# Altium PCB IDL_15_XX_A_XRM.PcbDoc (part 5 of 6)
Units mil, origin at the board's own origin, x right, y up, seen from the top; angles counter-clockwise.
Board outline 6653.34 x 6653.34 mil, 6 copper layers (Top Layer - SIG1, Layer 2 - GND1, Layer 3 - PWR, Layer 4 - PWR, Layer 5 - GND2, Bottom Layer - SIG4), stack 59.843 mil thick; 613 components, 324 nets, 1673 pads, 2316 vias.
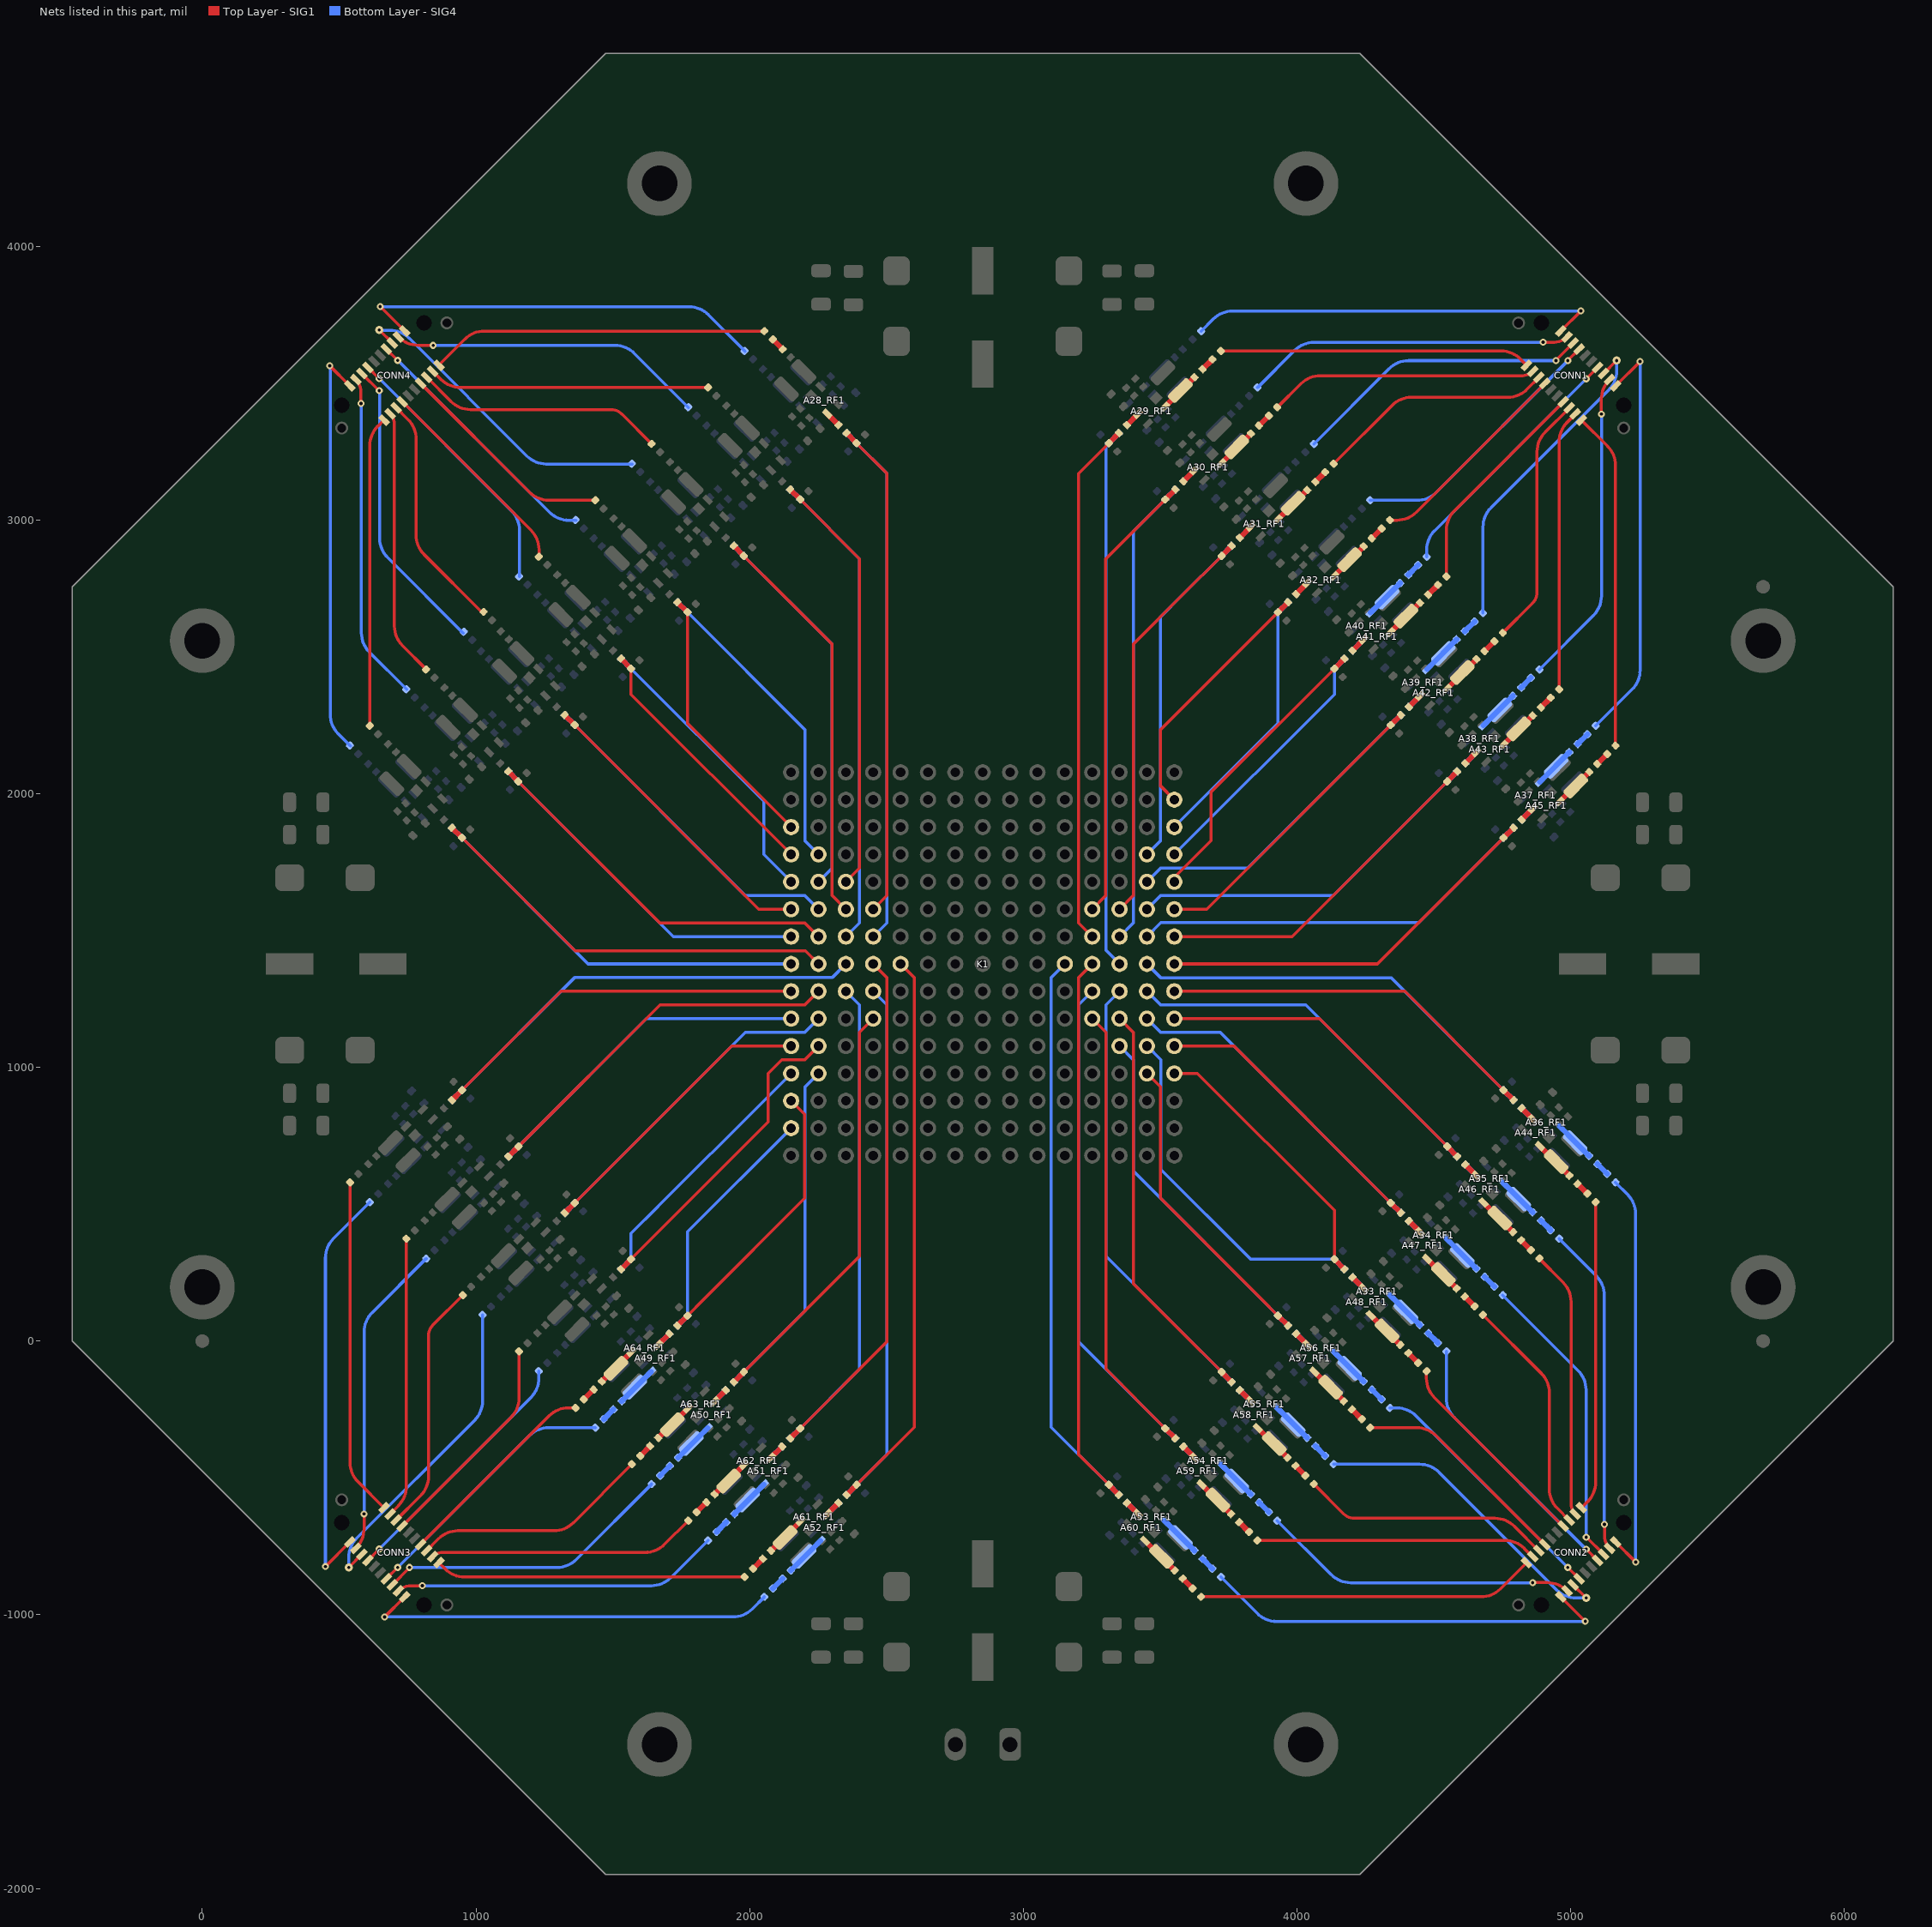
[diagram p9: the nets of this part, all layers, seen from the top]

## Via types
v1: diameter 25.59, hole 11.81, Layer 5 - GND2 to Bottom Layer - SIG4, tented both sides, 1069 vias
v2: diameter 25.59, hole 11.81, Top Layer - SIG1 to Layer 2 - GND1, tented both sides, 851 vias
v3: diameter 25.59, hole 11.81, Top Layer - SIG1 to Bottom Layer - SIG4, tented both sides, 384 vias
v4: diameter 29.53, hole 11.81, Top Layer - SIG1 to Bottom Layer - SIG4, tented both sides, 8 vias
v5: diameter 29.53, hole 11.81, Top Layer - SIG1 to Layer 2 - GND1, tented both sides, 4 vias

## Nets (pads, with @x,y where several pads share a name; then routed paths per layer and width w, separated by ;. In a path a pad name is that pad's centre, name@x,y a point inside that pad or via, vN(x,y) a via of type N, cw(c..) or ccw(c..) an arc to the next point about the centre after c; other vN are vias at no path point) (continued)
NetA28_C13_2: A28_C13.2 A28_L2.1 | length 51.2
  Top Layer - SIG1 w20: A28_L2.1@2084.38,3659.48 A28_C13.2@2120.57,3623.29
NetA28_Cin_1_2: A28_Cin_1.2 A28_RF1.3 | length 58.1
  Top Layer - SIG1 w20: A28_RF1.3@2283.42,3388.05 A28_Cin_1.2@2324.49,3346.99
NetA29_C13_1: A29_C13.1 A29_L1.1 A29_RF1.1 | length 153
  Top Layer - SIG1 w20: A29_RF1.1@3517.02,3413.31 A29_L1.1@3575.09,3471.37 ; A29_L1.1@3575.34,3471.37 A29_C13.1@3625.45,3521.48
NetA29_C13_2: A29_C13.2 A29_L2.1 | length 51.2
  Top Layer - SIG1 w20: A29_C13.2@3654.68,3550.71 A29_L2.1@3690.87,3586.9
NetA29_Cin_1_2: A29_Cin_1.2 A29_RF1.3 | length 58.1
  Top Layer - SIG1 w20: A29_Cin_1.2@3378.38,3346.79 A29_RF1.3@3419.44,3387.85
NetA30_C13_1: A30_C13.1 A30_L1.1 A30_RF1.1 | length 153
  Top Layer - SIG1 w20: A30_RF1.1@3723.03,3207.3 A30_L1.1@3781.09,3265.36 ; A30_L1.1@3781.35,3265.36 A30_C13.1@3831.46,3315.47
NetA30_C13_2: A30_C13.2 A30_L2.1 | length 51.2
  Top Layer - SIG1 w20: A30_C13.2@3860.69,3344.7 A30_L2.1@3896.88,3380.89
NetA30_Cin_1_2: A30_Cin_1.2 A30_RF1.3 | length 58.1
  Top Layer - SIG1 w20: A30_Cin_1.2@3584.39,3140.78 A30_RF1.3@3625.45,3181.84
NetA31_C13_1: A31_C13.1 A31_L1.1 A31_RF1.1 | length 153
  Top Layer - SIG1 w20: A31_RF1.1@3929.04,3001.29 A31_L1.1@3987.1,3059.35 ; A31_L1.1@3987.36,3059.35 A31_C13.1@4037.47,3109.46
NetA31_C13_2: A31_C13.2 A31_L2.1 | length 51.2
  Top Layer - SIG1 w20: A31_C13.2@4066.7,3138.69 A31_L2.1@4102.89,3174.88
NetA31_Cin_1_2: A31_Cin_1.2 A31_RF1.3 | length 58.1
  Top Layer - SIG1 w20: A31_Cin_1.2@3790.4,2934.77 A31_RF1.3@3831.46,2975.84
NetA32_C13_1: A32_C13.1 A32_L1.1 A32_RF1.1 | length 153
  Top Layer - SIG1 w20: A32_RF1.1@4135.05,2795.28 A32_L1.1@4193.11,2853.34 ; A32_L1.1@4193.36,2853.34 A32_C13.1@4243.47,2903.45
NetA32_C13_2: A32_C13.2 A32_L2.1 | length 51.2
  Top Layer - SIG1 w20: A32_C13.2@4272.7,2932.69 A32_L2.1@4308.89,2968.88
NetA32_Cin_1_2: A32_Cin_1.2 A32_RF1.3 | length 58.1
  Top Layer - SIG1 w20: A32_Cin_1.2@3996.4,2728.77 A32_RF1.3@4037.47,2769.83
NetA33_C13_1: A33_C13.1 A33_L1.1 A33_RF1.1 | length 153
  Bottom Layer - SIG4 w20: A33_RF1.1@4341.09,166.46 A33_L1.1@4399.15,108.4 ; A33_L1.1@4399.4,108.4 A33_C13.1@4449.51,58.29
NetA33_C13_2: A33_C13.2 A33_L2.1 | length 51.2
  Bottom Layer - SIG4 w20: A33_C13.2@4478.74,29.06 A33_L2.1@4514.93,-7.13
NetA33_Cin_1_2: A33_Cin_1.2 A33_RF1.3 | length 58.1
  Bottom Layer - SIG4 w20: A33_Cin_1.2@4202.44,232.98 A33_RF1.3@4243.51,191.92
NetA34_C13_1: A34_C13.1 A34_L1.1 A34_RF1.1 | length 153
  Bottom Layer - SIG4 w20: A34_RF1.1@4547.09,372.47 A34_L1.1@4605.16,314.41 ; A34_L1.1@4605.41,314.41 A34_C13.1@4655.52,264.3
NetA34_C13_2: A34_C13.2 A34_L2.1 | length 51.2
  Bottom Layer - SIG4 w20: A34_C13.2@4684.75,235.07 A34_L2.1@4720.94,198.88
NetA34_Cin_1_2: A34_Cin_1.2 A34_RF1.3 | length 58.1
  Bottom Layer - SIG4 w20: A34_Cin_1.2@4408.45,438.99 A34_RF1.3@4449.51,397.93
NetA35_C13_1: A35_C13.1 A35_L1.1 A35_RF1.1 | length 153
  Bottom Layer - SIG4 w20: A35_RF1.1@4753.1,578.48 A35_L1.1@4811.16,520.42 ; A35_L1.1@4811.42,520.42 A35_C13.1@4861.53,470.31
NetA35_C13_2: A35_C13.2 A35_L2.1 | length 51.2
  Bottom Layer - SIG4 w20: A35_C13.2@4890.76,441.08 A35_L2.1@4926.95,404.89
NetA35_Cin_1_2: A35_Cin_1.2 A35_RF1.3 | length 58.1
  Bottom Layer - SIG4 w20: A35_Cin_1.2@4614.46,645 A35_RF1.3@4655.52,603.94
NetA36_C13_1: A36_C13.1 A36_L1.1 A36_RF1.1 | length 153
  Bottom Layer - SIG4 w20: A36_RF1.1@4959.11,784.49 A36_L1.1@5017.17,726.43 ; A36_L1.1@5017.43,726.43 A36_C13.1@5067.54,676.32
NetA36_C13_2: A36_C13.2 A36_L2.1 | length 51.2
  Bottom Layer - SIG4 w20: A36_C13.2@5096.77,647.09 A36_L2.1@5132.96,610.9
NetA36_Cin_1_2: A36_Cin_1.2 A36_RF1.3 | length 58.1
  Bottom Layer - SIG4 w20: A36_Cin_1.2@4820.47,851.01 A36_RF1.3@4861.53,809.94
NetA37_C13_1: A37_C13.1 A37_L1.1 A37_RF1.1 | length 153
  Bottom Layer - SIG4 w20: A37_RF1.1@4886.99,2043.34 A37_L1.1@4945.05,2101.41 ; A37_L1.1@4945.05,2101.66 A37_C13.1@4995.16,2151.77
NetA37_C13_2: A37_C13.2 A37_L2.1 | length 51.2
  Bottom Layer - SIG4 w20: A37_C13.2@5024.39,2181 A37_L2.1@5060.58,2217.19
NetA37_Cin_1_2: A37_Cin_1.2 A37_RF1.3 | length 58.1
  Bottom Layer - SIG4 w20: A37_Cin_1.2@4820.47,1904.7 A37_RF1.3@4861.53,1945.76
NetA38_C13_1: A38_C13.1 A38_L1.1 A38_RF1.1 | length 153
  Bottom Layer - SIG4 w20: A38_RF1.1@4680.98,2249.35 A38_L1.1@4739.04,2307.41 ; A38_L1.1@4739.04,2307.67 A38_C13.1@4789.15,2357.78
NetA38_C13_2: A38_C13.2 A38_L2.1 | length 51.2
  Bottom Layer - SIG4 w20: A38_C13.2@4818.38,2387.01 A38_L2.1@4854.57,2423.2
NetA38_Cin_1_2: A38_Cin_1.2 A38_RF1.3 | length 58.1
  Bottom Layer - SIG4 w20: A38_Cin_1.2@4614.46,2110.71 A38_RF1.3@4655.52,2151.77
NetA39_C13_1: A39_C13.1 A39_L1.1 A39_RF1.1 | length 153
  Bottom Layer - SIG4 w20: A39_RF1.1@4474.97,2455.36 A39_L1.1@4533.03,2513.42 ; A39_L1.1@4533.03,2513.68 A39_C13.1@4583.14,2563.79
NetA39_C13_2: A39_C13.2 A39_L2.1 | length 51.2
  Bottom Layer - SIG4 w20: A39_C13.2@4612.37,2593.02 A39_L2.1@4648.56,2629.21
NetA39_Cin_1_2: A39_Cin_1.2 A39_RF1.3 | length 58.1
  Bottom Layer - SIG4 w20: A39_Cin_1.2@4408.45,2316.72 A39_RF1.3@4449.51,2357.78
NetA40_C13_1: A40_C13.1 A40_L1.1 A40_RF1.1 | length 153
  Bottom Layer - SIG4 w20: A40_RF1.1@4268.96,2661.37 A40_L1.1@4327.02,2719.43 ; A40_L1.1@4327.02,2719.68 A40_C13.1@4377.13,2769.79
NetA40_C13_2: A40_C13.2 A40_L2.1 | length 51.2
  Bottom Layer - SIG4 w20: A40_C13.2@4406.36,2799.03 A40_L2.1@4442.55,2835.22
NetA40_Cin_1_2: A40_Cin_1.2 A40_RF1.3 | length 58.1
  Bottom Layer - SIG4 w20: A40_Cin_1.2@4202.44,2522.72 A40_RF1.3@4243.51,2563.79
NetA41_C13_1: A41_C13.1 A41_L1.1 A41_RF1.1 | length 153
  Top Layer - SIG1 w20: A41_RF1.1@4341.09,2589.24 A41_L1.1@4399.15,2647.3 ; A41_L1.1@4399.4,2647.3 A41_C13.1@4449.51,2697.41
NetA41_C13_2: A41_C13.2 A41_L2.1 | length 51.2
  Top Layer - SIG1 w20: A41_C13.2@4478.75,2726.64 A41_L2.1@4514.94,2762.83
NetA41_Cin_1_2: A41_Cin_1.2 A41_RF1.3 | length 58.1
  Top Layer - SIG1 w20: A41_Cin_1.2@4202.44,2522.72 A41_RF1.3@4243.51,2563.79
NetA42_C13_1: A42_C13.1 A42_L1.1 A42_RF1.1 | length 153
  Top Layer - SIG1 w20: A42_RF1.1@4547.1,2383.24 A42_L1.1@4605.16,2441.3 ; A42_L1.1@4605.41,2441.3 A42_C13.1@4655.52,2491.41
NetA42_C13_2: A42_C13.2 A42_L2.1 | length 51.2
  Top Layer - SIG1 w20: A42_C13.2@4684.75,2520.64 A42_L2.1@4720.94,2556.83
NetA42_Cin_1_2: A42_Cin_1.2 A42_RF1.3 | length 58.1
  Top Layer - SIG1 w20: A42_Cin_1.2@4408.45,2316.72 A42_RF1.3@4449.51,2357.78
NetA43_C13_1: A43_C13.1 A43_L1.1 A43_RF1.1 | length 153
  Top Layer - SIG1 w20: A43_RF1.1@4753.1,2177.23 A43_L1.1@4811.16,2235.29 ; A43_L1.1@4811.42,2235.29 A43_C13.1@4861.53,2285.4
NetA43_C13_2: A43_C13.2 A43_L2.1 | length 51.2
  Top Layer - SIG1 w20: A43_C13.2@4890.76,2314.63 A43_L2.1@4926.95,2350.82
NetA43_Cin_1_2: A43_Cin_1.2 A43_RF1.3 | length 58.1
  Top Layer - SIG1 w20: A43_Cin_1.2@4614.46,2110.71 A43_RF1.3@4655.52,2151.77
NetA44_C13_1: A44_C13.1 A44_L1.1 A44_RF1.1 | length 153
  Top Layer - SIG1 w20: A44_RF1.1@4886.99,712.36 A44_L1.1@4945.05,654.3 ; A44_L1.1@4945.05,654.05 A44_C13.1@4995.16,603.94
NetA44_C13_2: A44_C13.2 A44_L2.1 | length 51.2
  Top Layer - SIG1 w20: A44_C13.2@5024.39,574.71 A44_L2.1@5060.58,538.51
NetA44_Cin_1_2: A44_Cin_1.2 A44_RF1.3 | length 58.1
  Top Layer - SIG1 w20: A44_Cin_1.2@4820.47,851.01 A44_RF1.3@4861.53,809.94
NetA45_C13_1: A45_C13.1 A45_L1.1 A45_RF1.1 | length 153
  Top Layer - SIG1 w20: A45_RF1.1@4959.11,1971.22 A45_L1.1@5017.17,2029.28 ; A45_L1.1@5017.43,2029.28 A45_C13.1@5067.54,2079.39
NetA45_C13_2: A45_C13.2 A45_L2.1 | length 51.2
  Top Layer - SIG1 w20: A45_C13.2@5096.77,2108.62 A45_L2.1@5132.96,2144.81
NetA45_Cin_1_2: A45_Cin_1.2 A45_RF1.3 | length 58.1
  Top Layer - SIG1 w20: A45_Cin_1.2@4820.47,1904.7 A45_RF1.3@4861.53,1945.76
NetA46_C13_1: A46_C13.1 A46_L1.1 A46_RF1.1 | length 153
  Top Layer - SIG1 w20: A46_RF1.1@4680.98,506.36 A46_L1.1@4739.04,448.29 ; A46_L1.1@4739.04,448.04 A46_C13.1@4789.15,397.93
NetA46_C13_2: A46_C13.2 A46_L2.1 | length 51.2
  Top Layer - SIG1 w20: A46_C13.2@4818.38,368.7 A46_L2.1@4854.57,332.51
NetA46_Cin_1_2: A46_Cin_1.2 A46_RF1.3 | length 58.1
  Top Layer - SIG1 w20: A46_Cin_1.2@4614.46,645 A46_RF1.3@4655.52,603.94
NetA47_C13_1: A47_C13.1 A47_L1.1 A47_RF1.1 | length 153
  Top Layer - SIG1 w20: A47_RF1.1@4474.97,300.35 A47_L1.1@4533.03,242.29 ; A47_L1.1@4533.03,242.03 A47_C13.1@4583.14,191.92
NetA47_C13_2: A47_C13.2 A47_L2.1 | length 51.2
  Top Layer - SIG1 w20: A47_C13.2@4612.37,162.69 A47_L2.1@4648.56,126.5
NetA47_Cin_1_2: A47_Cin_1.2 A47_RF1.3 | length 58.1
  Top Layer - SIG1 w20: A47_Cin_1.2@4408.45,438.99 A47_RF1.3@4449.51,397.93
NetA48_C13_1: A48_C13.1 A48_L1.1 A48_RF1.1 | length 153
  Top Layer - SIG1 w20: A48_RF1.1@4268.96,94.34 A48_L1.1@4327.02,36.28 ; A48_L1.1@4327.02,36.02 A48_C13.1@4377.13,-14.09
NetA48_C13_2: A48_C13.2 A48_L2.1 | length 51.2
  Top Layer - SIG1 w20: A48_C13.2@4406.36,-43.32 A48_L2.1@4442.55,-79.51
NetA48_Cin_1_2: A48_Cin_1.2 A48_RF1.3 | length 58.1
  Top Layer - SIG1 w20: A48_Cin_1.2@4202.44,232.98 A48_RF1.3@4243.51,191.92
NetA49_C13_1: A49_C13.1 A49_L1.1 A49_RF1.1 | length 153
  Bottom Layer - SIG4 w20: A49_C13.1@1531.87,-220.13 A49_L1.1@1581.98,-170.02 ; A49_L1.1@1581.98,-169.76 A49_RF1.1@1640.04,-111.7
NetA49_C13_2: A49_C13.2 A49_L2.1 | length 51.2
  Bottom Layer - SIG4 w20: A49_L2.1@1466.45,-285.55 A49_C13.2@1502.64,-249.36
NetA49_Cin_1_2: A49_Cin_1.2 A49_RF1.3 | length 58.1
  Bottom Layer - SIG4 w20: A49_RF1.3@1665.49,-14.12 A49_Cin_1.2@1706.56,26.94
NetA50_C13_1: A50_C13.1 A50_L1.1 A50_RF1.1 | length 153
  Bottom Layer - SIG4 w20: A50_C13.1@1737.91,-426.17 A50_L1.1@1788.02,-376.06 ; A50_L1.1@1788.02,-375.8 A50_RF1.1@1846.08,-317.74
NetA50_C13_2: A50_C13.2 A50_L2.1 | length 51.2
  Bottom Layer - SIG4 w20: A50_L2.1@1672.49,-491.59 A50_C13.2@1708.68,-455.4
NetA50_Cin_1_2: A50_Cin_1.2 A50_RF1.3 | length 58.1
  Bottom Layer - SIG4 w20: A50_RF1.3@1871.53,-220.16 A50_Cin_1.2@1912.6,-179.1
NetA51_C13_1: A51_C13.1 A51_L1.1 A51_RF1.1 | length 153
  Bottom Layer - SIG4 w20: A51_C13.1@1943.92,-632.18 A51_L1.1@1994.03,-582.07 ; A51_L1.1@1994.03,-581.81 A51_RF1.1@2052.09,-523.75
NetA51_C13_2: A51_C13.2 A51_L2.1 | length 51.2
  Bottom Layer - SIG4 w20: A51_L2.1@1878.5,-697.6 A51_C13.2@1914.69,-661.41
NetA51_Cin_1_2: A51_Cin_1.2 A51_RF1.3 | length 58.1
  Bottom Layer - SIG4 w20: A51_RF1.3@2077.54,-426.17 A51_Cin_1.2@2118.61,-385.11
NetA52_C13_1: A52_C13.1 A52_L1.1 A52_RF1.1 | length 153
  Bottom Layer - SIG4 w20: A52_C13.1@2149.92,-838.18 A52_L1.1@2200.03,-788.07 ; A52_L1.1@2200.03,-787.82 A52_RF1.1@2258.09,-729.76
NetA52_C13_2: A52_C13.2 A52_L2.1 | length 51.2
  Bottom Layer - SIG4 w20: A52_L2.1@2084.5,-903.61 A52_C13.2@2120.69,-867.42
NetA52_Cin_1_2: A52_Cin_1.2 A52_RF1.3 | length 58.1
  Bottom Layer - SIG4 w20: A52_RF1.3@2283.55,-632.18 A52_Cin_1.2@2324.61,-591.11
NetA53_C13_1: A53_C13.1 A53_L1.1 A53_RF1.1 | length 153
  Bottom Layer - SIG4 w20: A53_RF1.1@3516.99,-657.63 A53_L1.1@3575.05,-715.69 ; A53_L1.1@3575.31,-715.69 A53_C13.1@3625.42,-765.8
NetA53_C13_2: A53_C13.2 A53_L2.1 | length 51.2
  Bottom Layer - SIG4 w20: A53_C13.2@3654.65,-795.03 A53_L2.1@3690.84,-831.22
NetA53_Cin_1_2: A53_Cin_1.2 A53_RF1.3 | length 58.1
  Bottom Layer - SIG4 w20: A53_Cin_1.2@3378.35,-591.11 A53_RF1.3@3419.41,-632.18
NetA54_C13_1: A54_C13.1 A54_L1.1 A54_RF1.1 | length 153
  Bottom Layer - SIG4 w20: A54_RF1.1@3723,-451.62 A54_L1.1@3781.06,-509.69 ; A54_L1.1@3781.31,-509.68 A54_C13.1@3831.42,-559.79
NetA54_C13_2: A54_C13.2 A54_L2.1 | length 51.2
  Bottom Layer - SIG4 w20: A54_C13.2@3860.66,-589.03 A54_L2.1@3896.85,-625.22
NetA54_Cin_1_2: A54_Cin_1.2 A54_RF1.3 | length 58.1
  Bottom Layer - SIG4 w20: A54_Cin_1.2@3584.35,-385.11 A54_RF1.3@3625.42,-426.17
NetA55_C13_1: A55_C13.1 A55_L1.1 A55_RF1.1 | length 153
  Bottom Layer - SIG4 w20: A55_RF1.1@3929.01,-245.62 A55_L1.1@3987.07,-303.68 ; A55_L1.1@3987.32,-303.68 A55_C13.1@4037.43,-353.79
NetA55_C13_2: A55_C13.2 A55_L2.1 | length 51.2
  Bottom Layer - SIG4 w20: A55_C13.2@4066.66,-383.02 A55_L2.1@4102.85,-419.21
NetA55_Cin_1_2: A55_Cin_1.2 A55_RF1.3 | length 58.1
  Bottom Layer - SIG4 w20: A55_Cin_1.2@3790.36,-179.1 A55_RF1.3@3831.42,-220.16
NetA56_C13_1: A56_C13.1 A56_L1.1 A56_RF1.1 | length 153
  Bottom Layer - SIG4 w20: A56_RF1.1@4135.05,-39.58 A56_L1.1@4193.11,-97.64 ; A56_L1.1@4193.36,-97.64 A56_C13.1@4243.47,-147.75
NetA56_C13_2: A56_C13.2 A56_L2.1 | length 51.2
  Bottom Layer - SIG4 w20: A56_C13.2@4272.7,-176.98 A56_L2.1@4308.89,-213.17
NetA56_Cin_1_2: A56_Cin_1.2 A56_RF1.3 | length 58.1
  Bottom Layer - SIG4 w20: A56_Cin_1.2@3996.4,26.94 A56_RF1.3@4037.47,-14.12
NetA57_C13_1: A57_C13.1 A57_L1.1 A57_RF1.1 | length 153
  Top Layer - SIG1 w20: A57_RF1.1@4062.92,-111.7 A57_L1.1@4120.98,-169.76 ; A57_L1.1@4120.98,-170.02 A57_C13.1@4171.09,-220.13
NetA57_C13_2: A57_C13.2 A57_L2.1 | length 51.2
  Top Layer - SIG1 w20: A57_C13.2@4200.32,-249.36 A57_L2.1@4236.51,-285.55
NetA57_Cin_1_2: A57_Cin_1.2 A57_RF1.3 | length 58.1
  Top Layer - SIG1 w20: A57_Cin_1.2@3996.4,26.94 A57_RF1.3@4037.47,-14.12
NetA58_C13_1: A58_C13.1 A58_L1.1 A58_RF1.1 | length 153
  Top Layer - SIG1 w20: A58_RF1.1@3856.88,-317.74 A58_L1.1@3914.94,-375.8 ; A58_L1.1@3914.94,-376.06 A58_C13.1@3965.05,-426.17
NetA58_C13_2: A58_C13.2 A58_L2.1 | length 51.2
  Top Layer - SIG1 w20: A58_C13.2@3994.28,-455.4 A58_L2.1@4030.47,-491.59
NetA58_Cin_1_2: A58_Cin_1.2 A58_RF1.3 | length 58.1
  Top Layer - SIG1 w20: A58_Cin_1.2@3790.36,-179.1 A58_RF1.3@3831.42,-220.16
NetA59_C13_1: A59_C13.1 A59_L1.1 A59_RF1.1 | length 153
  Top Layer - SIG1 w20: A59_RF1.1@3650.87,-523.75 A59_L1.1@3708.93,-581.81 ; A59_L1.1@3708.93,-582.07 A59_C13.1@3759.04,-632.18
NetA59_C13_2: A59_C13.2 A59_L2.1 | length 51.2
  Top Layer - SIG1 w20: A59_C13.2@3788.27,-661.41 A59_L2.1@3824.46,-697.6
NetA59_Cin_1_2: A59_Cin_1.2 A59_RF1.3 | length 58.1
  Top Layer - SIG1 w20: A59_Cin_1.2@3584.35,-385.11 A59_RF1.3@3625.42,-426.17
NetA60_C13_1: A60_C13.1 A60_L1.1 A60_RF1.1 | length 153
  Top Layer - SIG1 w20: A60_RF1.1@3444.87,-729.76 A60_L1.1@3502.93,-787.82 ; A60_L1.1@3502.93,-788.07 A60_C13.1@3553.04,-838.18
NetA60_C13_2: A60_C13.2 A60_L2.1 | length 51.2
  Top Layer - SIG1 w20: A60_C13.2@3582.27,-867.41 A60_L2.1@3618.46,-903.6
NetA60_Cin_1_2: A60_Cin_1.2 A60_RF1.3 | length 58.1
  Top Layer - SIG1 w20: A60_Cin_1.2@3378.35,-591.11 A60_RF1.3@3419.41,-632.18
NetA61_C13_1: A61_C13.1 A61_L1.1 A61_RF1.1 | length 153
  Top Layer - SIG1 w20: A61_C13.1@2077.54,-765.8 A61_L1.1@2127.65,-715.69 ; A61_L1.1@2127.91,-715.69 A61_RF1.1@2185.97,-657.63
NetA61_C13_2: A61_C13.2 A61_L2.1 | length 51.2
  Top Layer - SIG1 w20: A61_L2.1@2012.12,-831.22 A61_C13.2@2048.31,-795.03
NetA61_Cin_1_2: A61_Cin_1.2 A61_RF1.3 | length 58.1
  Top Layer - SIG1 w20: A61_RF1.3@2283.55,-632.18 A61_Cin_1.2@2324.61,-591.11
NetA62_C13_1: A62_C13.1 A62_L1.1 A62_RF1.1 | length 153
  Top Layer - SIG1 w20: A62_C13.1@1871.54,-559.8 A62_L1.1@1921.65,-509.69 ; A62_L1.1@1921.9,-509.69 A62_RF1.1@1979.96,-451.63
NetA62_C13_2: A62_C13.2 A62_L2.1 | length 51.2
  Top Layer - SIG1 w20: A62_L2.1@1806.11,-625.22 A62_C13.2@1842.3,-589.03
NetA62_Cin_1_2: A62_Cin_1.2 A62_RF1.3 | length 58.1
  Top Layer - SIG1 w20: A62_RF1.3@2077.54,-426.17 A62_Cin_1.2@2118.61,-385.11
NetA63_C13_1: A63_C13.1 A63_L1.1 A63_RF1.1 | length 153
  Top Layer - SIG1 w20: A63_C13.1@1665.53,-353.79 A63_L1.1@1715.64,-303.68 ; A63_L1.1@1715.89,-303.68 A63_RF1.1@1773.95,-245.62
NetA63_C13_2: A63_C13.2 A63_L2.1 | length 51.2
  Top Layer - SIG1 w20: A63_L2.1@1600.11,-419.21 A63_C13.2@1636.3,-383.02
NetA63_Cin_1_2: A63_Cin_1.2 A63_RF1.3 | length 58.1
  Top Layer - SIG1 w20: A63_RF1.3@1871.54,-220.16 A63_Cin_1.2@1912.6,-179.1
NetA64_C13_1: A64_C13.1 A64_L1.1 A64_RF1.1 | length 153
  Top Layer - SIG1 w20: A64_C13.1@1459.49,-147.75 A64_L1.1@1509.6,-97.64 ; A64_L1.1@1509.85,-97.64 A64_RF1.1@1567.91,-39.58
NetA64_C13_2: A64_C13.2 A64_L2.1 | length 51.2
  Top Layer - SIG1 w20: A64_L2.1@1394.07,-213.17 A64_C13.2@1430.26,-176.98
NetA64_Cin_1_2: A64_Cin_1.2 A64_RF1.3 | length 58.1
  Top Layer - SIG1 w20: A64_RF1.3@1665.49,-14.12 A64_Cin_1.2@1706.56,26.94
RF1: A1_Cin_1.1 A1_Rin_1.2 K1.P5 | length 1163.6
  Top Layer - SIG1 w11: A1_Rin_1.2@1566.63,299.1 2067.94,800.4 2067.94,978 2117.89,1027.95 2201.43,1027.95 K1.P5@2251.43,1077.95
  Top Layer - SIG1 w20: A1_Cin_1.1@1529.75,262.21 A1_Rin_1.2@1566.63,299.1
RF2: A2_Cin_1.1 A2_Rin_1.2 K1.R5 | length 1142.4
  Top Layer - SIG1 w11: A2_Rin_1.2@1360.98,504.75 1934.18,1077.95 ; 1996.51,1077.95 1934.18,1077.95 ; K1.R5@2151.43,1077.95 1934.18,1077.95
  Top Layer - SIG1 w20: A2_Cin_1.1@1324.1,467.86 A2_Rin_1.2@1360.98,504.75
RF3: A3_Cin_1.1 A3_Rin_1.2 K1.P7 | length 1383.6
  Top Layer - SIG1 w11: A3_Rin_1.2@1154.97,710.76 1672.17,1227.95 1735.72,1227.95 2201.43,1227.95 K1.P7@2251.43,1277.95
  Top Layer - SIG1 w20: A3_Cin_1.1@1118.09,673.87 A3_Rin_1.2@1154.97,710.76
RF4: A4_Cin_1.1 A4_Rin_1.2 K1.R7 | length 1404.2
  Top Layer - SIG1 w11: A4_Rin_1.2@948.97,916.77 1310.15,1277.95 K1.R7@2151.43,1277.95
  Top Layer - SIG1 w20: A4_Cin_1.1@912.08,879.88 A4_Rin_1.2@948.97,916.77
RF5: A5_Cin_1.1 A5_Rin_1.2 K1.P8 | length 1546
  Top Layer - SIG1 w11: A5_Rin_1.2@948.52,1838.78 1362.06,1425.24 1546.63,1425.24 2204.14,1425.24 K1.P8@2251.43,1377.95
  Top Layer - SIG1 w20: A5_Cin_1.1@911.63,1875.67 A5_Rin_1.2@948.52,1838.78
RF6: A6_Cin_1.1 A6_Rin_1.2 K1.P9 | length 1383.9
  Top Layer - SIG1 w11: A6_Rin_1.2@1154.52,2044.79 1671,1528.32 1734.9,1528.32 2201.07,1528.32 K1.P9@2251.43,1477.95
  Top Layer - SIG1 w20: A6_Cin_1.1@1117.64,2081.68 A6_Rin_1.2@1154.52,2044.79
RF7: A7_Cin_1.1 A7_Rin_1.2 K1.R10 | length 1121.8
  Top Layer - SIG1 w11: A7_Rin_1.2@1360.53,2250.8 2033.38,1577.95 K1.R10@2151.43,1577.95
  Top Layer - SIG1 w20: A7_Cin_1.1@1323.65,2287.68 A7_Rin_1.2@1360.53,2250.8
RF8: A8_Cin_1.1 A8_Rin_1.2 K1.R12 | length 973.3
  Top Layer - SIG1 w11: A8_Rin_1.2@1566.54,2456.81 1566.54,2362.85 K1.R12@2151.43,1777.95
  Top Layer - SIG1 w20: A8_Cin_1.1@1529.65,2493.69 A8_Rin_1.2@1566.54,2456.81
RF9: A9_Cin_1.1 A9_Rin_1.2 K1.R11 | length 1073.3
  Bottom Layer - SIG4 w11: A9_Rin_1.2@1566.54,2456.81 2051.43,1971.91 2051.43,1777.95 K1.R11@2151.43,1677.95
  Bottom Layer - SIG4 w20: A9_Cin_1.1@1529.65,2493.69 A9_Rin_1.2@1566.54,2456.81
RF10: A10_Cin_1.1 A10_Rin_1.2 K1.P10 | length 1221.8
  Bottom Layer - SIG4 w11: A10_Rin_1.2@1360.53,2250.8 1983.38,1627.95 2201.43,1627.95 K1.P10@2251.43,1577.95
  Bottom Layer - SIG4 w20: A10_Cin_1.1@1323.65,2287.68 A10_Rin_1.2@1360.53,2250.8
RF11: A11_Cin_1.1 A11_Rin_1.2 K1.R9 | length 1283.9
  Bottom Layer - SIG4 w11: A11_Rin_1.2@1154.52,2044.79 1721.36,1477.95 K1.R9@2151.43,1477.95
  Bottom Layer - SIG4 w20: A11_Cin_1.1@1117.64,2081.68 A11_Rin_1.2@1154.52,2044.79
RF12: A12_Cin_1.1 A12_Rin_1.2 K1.R8 | length 1446
  Bottom Layer - SIG4 w11: A12_Rin_1.2@948.52,1838.78 1409.35,1377.95 K1.R8@2151.43,1377.95
  Bottom Layer - SIG4 w20: A12_Cin_1.1@911.63,1875.67 A12_Rin_1.2@948.52,1838.78
RF13: A13_Cin_1.1 A13_Rin_1.2 K1.N8 | length 1652.5
  Bottom Layer - SIG4 w11: A13_Rin_1.2@948.97,923.65 A13_Rin_1.2@948.97,916.77 1360.15,1327.95 1697.33,1327.95 2301.43,1327.95 K1.N8@2351.43,1377.95
  Bottom Layer - SIG4 w20: A13_Cin_1.1@912.08,879.88 A13_Rin_1.2@948.97,916.77
RF14: A14_Cin_1.1 A14_Rin_1.2 K1.R6 | length 1242.1
  Bottom Layer - SIG4 w11: A14_Rin_1.2@1154.97,710.76 1622.17,1177.95 1838.67,1177.95 K1.R6@2151.43,1177.95
  Bottom Layer - SIG4 w20: A14_Cin_1.1@1118.09,673.87 A14_Rin_1.2@1154.97,710.76
RF15: A15_Cin_1.1 A15_Rin_1.2 K1.P6 | length 1221.5
  Bottom Layer - SIG4 w11: A15_Rin_1.2@1360.98,504.75 1984.18,1127.95 2201.43,1127.95 K1.P6@2251.43,1177.95
  Bottom Layer - SIG4 w20: A15_Cin_1.1@1324.1,467.86 A15_Rin_1.2@1360.98,504.75
RF16: A16_Cin_1.1 A16_Rin_1.2 K1.R4 | length 1113.1
  Bottom Layer - SIG4 w11: A16_Rin_1.2@1566.63,299.1 1566.63,393.15 ; 1665.49,492.01 1566.63,393.15 ; K1.R4@2151.43,977.95 1566.63,393.15
  Bottom Layer - SIG4 w20: A16_Cin_1.1@1529.75,262.21 A16_Rin_1.2@1566.63,299.1
RF17: A17_Cin_1.1 A17_Rin_1.2 K1.A13 | length 993.8
  Bottom Layer - SIG4 w11: K1.A13@3551.43,1877.95 3930.29,2256.81 A17_Rin_1.2@3930.29,2662.65
  Bottom Layer - SIG4 w20: A17_Rin_1.2@3930.29,2662.65 A17_Cin_1.1@3967.17,2699.53
RF18: A18_Cin_1.1 A18_Rin_1.2 K1.B12 | length 1255.9
  Bottom Layer - SIG4 w11: K1.B12@3451.43,1777.95 3501.43,1827.95 3501.43,2499.88 3501.43,2645.81 3579.5,2723.88 A18_Rin_1.2@3724.28,2868.66
  Bottom Layer - SIG4 w20: A18_Rin_1.2@3724.28,2868.66 A18_Cin_1.1@3761.17,2905.54
RF19: A19_Cin_1.1 A19_Rin_1.2 K1.C9 | length 1724.1
  Bottom Layer - SIG4 w11: K1.C9@3351.43,1477.95 3401.43,1527.95 3401.43,2957.82 A19_Rin_1.2@3518.27,3074.66 A19_Rin_1.2@3518.27,3068.59
  Bottom Layer - SIG4 w20: A19_Rin_1.2@3518.27,3074.66 A19_Cin_1.1@3555.16,3111.55
RF20: A20_Cin_1.1 A20_Rin_1.2 K1.C8 | length 1980.1
  Bottom Layer - SIG4 w11: A20_Rin_1.2@3312.26,3280.67 3301.43,3269.84 3301.43,1427.95 K1.C8@3351.43,1377.95
  Bottom Layer - SIG4 w20: A20_Rin_1.2@3312.26,3280.67 A20_Cin_1.1@3349.15,3317.56
RF21: A21_Cin_1.1 A21_Rin_1.2 K1.M9 | length 1921.7
  Bottom Layer - SIG4 w11: A21_Rin_1.2@2390.6,3280.87 2501.43,3170.04 2501.43,2373.9 2501.43,1527.95 K1.M9@2451.43,1477.95
  Bottom Layer - SIG4 w20: A21_Cin_1.1@2353.72,3317.76 A21_Rin_1.2@2390.6,3280.87
RF22: A22_Cin_1.1 A22_Rin_1.2 K1.N9 | length 1759.6
  Bottom Layer - SIG4 w11: A22_Rin_1.2@2184.6,3074.86 2401.43,2858.02 2401.43,1527.95 K1.N9@2351.43,1477.95
  Bottom Layer - SIG4 w20: A22_Cin_1.1@2147.71,3111.75 A22_Rin_1.2@2184.6,3074.86
RF23: A23_Cin_1.1 A23_Rin_1.2 K1.P11 | length 1397.5
  Bottom Layer - SIG4 w11: A23_Rin_1.2@1978.59,2868.85 2301.43,2546.01 2301.43,2399.33 2301.43,1727.95 K1.P11@2251.43,1677.95
  Bottom Layer - SIG4 w20: A23_Cin_1.1@1941.7,2905.74 A23_Rin_1.2@1978.59,2868.85
RF24: A24_Cin_1.1 A24_Rin_1.2 K1.P12 | length 1135.4
  Bottom Layer - SIG4 w11: A24_Rin_1.2@1772.58,2662.85 2201.43,2233.99 2201.43,2207.99 2201.43,1827.95 K1.P12@2251.43,1777.95
  Bottom Layer - SIG4 w20: A24_Cin_1.1@1735.69,2699.73 A24_Rin_1.2@1772.58,2662.85
RF25: A25_Cin_1.1 A25_Rin_1.2 K1.R13 | length 994
  Top Layer - SIG1 w11: A25_Rin_1.2@1772.58,2662.85 1772.58,2256.81 K1.R13@2151.43,1877.95
  Top Layer - SIG1 w20: A25_Cin_1.1@1735.69,2699.73 A25_Rin_1.2@1772.58,2662.85
RF26: A26_Cin_1.1 A26_Rin_1.2 K1.N10 | length 1497.5
  Top Layer - SIG1 w11: A26_Rin_1.2@1978.59,2868.85 2122.81,2724.63 2301.43,2546.01 2301.43,2299.77 2301.43,1627.95 K1.N10@2351.43,1577.95
  Top Layer - SIG1 w20: A26_Cin_1.1@1941.7,2905.74 A26_Rin_1.2@1978.59,2868.85
RF27: A27_Cin_1.1 A27_Rin_1.2 K1.N11 | length 1559.6
  Top Layer - SIG1 w11: A27_Rin_1.2@2184.6,3074.86 2401.43,2858.02 2401.43,1727.95 K1.N11@2351.43,1677.95
  Top Layer - SIG1 w20: A27_Cin_1.1@2147.71,3111.75 A27_Rin_1.2@2184.6,3074.86
RF28: A28_Cin_1.1 A28_Rin_1.2 K1.M10 | length 1821.7
  Top Layer - SIG1 w11: A28_Rin_1.2@2390.6,3280.87 2501.43,3170.04 2501.43,2273.9 2501.43,1627.95 K1.M10@2451.43,1577.95
  Top Layer - SIG1 w20: A28_Cin_1.1@2353.72,3317.76 A28_Rin_1.2@2390.6,3280.87
RF29: A29_Cin_1.1 A29_Rin_1.2 K1.D9 | length 1921.5
  Top Layer - SIG1 w11: K1.D9@3251.43,1477.95 3201.43,1527.95 3201.43,3169.84 A29_Rin_1.2@3312.26,3280.67
  Top Layer - SIG1 w20: A29_Rin_1.2@3312.26,3280.67 A29_Cin_1.1@3349.15,3317.56
RF30: A30_Cin_1.1 A30_Rin_1.2 K1.D10 | length 1659.4
  Top Layer - SIG1 w11: K1.D10@3251.43,1577.95 3300.88,1627.4 3300.88,2857.27 A30_Rin_1.2@3518.27,3074.66
  Top Layer - SIG1 w20: A30_Rin_1.2@3518.27,3074.66 A30_Cin_1.1@3555.16,3111.55
RF31: A31_Cin_1.1 A31_Rin_1.2 K1.C10 | length 1497.3
  Top Layer - SIG1 w11: K1.C10@3351.43,1577.95 3401.43,1627.95 3401.43,2299.88 3401.43,2545.81 3579.5,2723.88 A31_Rin_1.2@3724.28,2868.66
  Top Layer - SIG1 w20: A31_Rin_1.2@3724.28,2868.66 A31_Cin_1.1@3761.17,2905.54
RF32: A32_Cin_1.1 A32_Rin_1.2 K1.A14 | length 935.2
  Top Layer - SIG1 w11: K1.A14@3551.43,1977.95 3501.43,2027.95 3501.43,2233.79 A32_Rin_1.2@3930.29,2662.65
  Top Layer - SIG1 w20: A32_Rin_1.2@3930.29,2662.65 A32_Cin_1.1@3967.17,2699.53
RF33: A33_Cin_1.1 A33_Rin_1.2 K1.B5 | length 1293.3
  Bottom Layer - SIG4 w11: K1.B5@3452.86,1077.95 3502.86,1027.95 3502.86,626.75 3830.52,299.1 A33_Rin_1.2@4136.33,299.1
  Bottom Layer - SIG4 w20: A33_Rin_1.2@4136.33,299.1 A33_Cin_1.1@4173.21,262.21
RF34: A34_Cin_1.1 A34_Rin_1.2 K1.B6 | length 1221.8
  Bottom Layer - SIG4 w11: K1.B6@3451.43,1177.95 3501.43,1127.95 3719.49,1127.95 A34_Rin_1.2@4342.33,505.11
  Bottom Layer - SIG4 w20: A34_Rin_1.2@4342.33,505.11 A34_Cin_1.1@4379.22,468.22
RF35: A35_Cin_1.1 A35_Rin_1.2 K1.B7 | length 1383.9
  Bottom Layer - SIG4 w11: K1.B7@3451.43,1277.95 3501.43,1227.95 3701.43,1227.95 4031.5,1227.95 A35_Rin_1.2@4548.34,711.12
  Bottom Layer - SIG4 w20: A35_Rin_1.2@4548.34,711.12 A35_Cin_1.1@4585.23,674.23
RF36: A36_Cin_1.1 A36_Rin_1.2 K1.B8 | length 1546
  Bottom Layer - SIG4 w11: K1.B8@3451.43,1377.95 3501.66,1327.72 4343.75,1327.72 A36_Rin_1.2@4754.35,917.12
  Bottom Layer - SIG4 w20: A36_Rin_1.2@4754.35,917.12 A36_Cin_1.1@4791.24,880.24
RF37: A37_Cin_1.1 A37_Rin_1.2 K1.B9 | length 1504.5
  Bottom Layer - SIG4 w11: K1.B9@3451.43,1477.95 3502.86,1529.38 4445.15,1529.38 A37_Rin_1.2@4754.35,1838.58
  Bottom Layer - SIG4 w20: A37_Rin_1.2@4754.35,1838.58 A37_Cin_1.1@4791.24,1875.47
RF38: A38_Cin_1.1 A38_Rin_1.2 K1.B10 | length 1342.4
  Bottom Layer - SIG4 w11: K1.B10@3451.43,1577.95 3501.43,1627.95 4131.7,1627.95 A38_Rin_1.2@4548.34,2044.59
  Bottom Layer - SIG4 w20: A38_Rin_1.2@4548.34,2044.59 A38_Cin_1.1@4585.23,2081.48
RF39: A39_Cin_1.1 A39_Rin_1.2 K1.B11 | length 1180.3
  Bottom Layer - SIG4 w11: K1.B11@3451.43,1677.95 3501.43,1727.95 3819.69,1727.95 A39_Rin_1.2@4342.34,2250.6
  Bottom Layer - SIG4 w20: A39_Rin_1.2@4342.34,2250.6 A39_Cin_1.1@4379.22,2287.49
RF40: A40_Cin_1.1 A40_Rin_1.2 K1.A12 | length 973.1
  Bottom Layer - SIG4 w11: K1.A12@3551.43,1777.95 4136.33,2362.85 A40_Rin_1.2@4136.33,2456.61
  Bottom Layer - SIG4 w20: A40_Rin_1.2@4136.33,2456.61 A40_Cin_1.1@4173.21,2493.49
RF41: A41_Cin_1.1 A41_Rin_1.2 K1.A11 | length 1073.1
  Top Layer - SIG1 w11: K1.A11@3551.43,1677.95 3551.43,1693.46 3685.92,1827.95 3685.92,2006.2 A41_Rin_1.2@4136.33,2456.61
  Top Layer - SIG1 w20: A41_Rin_1.2@4136.33,2456.61 A41_Cin_1.1@4173.21,2493.49
RF42: A42_Cin_1.1 A42_Rin_1.2 K1.A10 | length 1121.7
  Top Layer - SIG1 w11: K1.A10@3551.43,1577.95 3669.69,1577.95 A42_Rin_1.2@4342.34,2250.6
  Top Layer - SIG1 w20: A42_Rin_1.2@4342.34,2250.6 A42_Cin_1.1@4379.22,2287.49
RF43: A43_Cin_1.1 A43_Rin_1.2 K1.A9 | length 1283.8
  Top Layer - SIG1 w11: K1.A9@3551.43,1477.95 3918.6,1477.95 3981.7,1477.95 A43_Rin_1.2@4548.34,2044.59
  Top Layer - SIG1 w20: A43_Rin_1.2@4548.34,2044.59 A43_Cin_1.1@4585.23,2081.48
RF44: A44_Cin_1.1 A44_Rin_1.2 K1.A7 | length 1404.5
  Top Layer - SIG1 w11: K1.A7@3551.43,1277.95 4393.52,1277.95 A44_Rin_1.2@4754.35,917.12
  Top Layer - SIG1 w20: A44_Rin_1.2@4754.35,917.12 A44_Cin_1.1@4791.24,880.24
RF45: A45_Cin_1.1 A45_Rin_1.2 K1.A8 | length 1445.9
  Top Layer - SIG1 w11: K1.A8@3551.43,1377.95 4097.82,1377.95 4293.72,1377.95 A45_Rin_1.2@4754.35,1838.58
  Top Layer - SIG1 w20: A45_Rin_1.2@4754.35,1838.58 A45_Cin_1.1@4791.24,1875.47
RF46: A46_Cin_1.1 A46_Rin_1.2 K1.A6 | length 1242.4
  Top Layer - SIG1 w11: K1.A6@3551.43,1177.95 4018.6,1177.95 4081.5,1177.95 A46_Rin_1.2@4548.34,711.12
  Top Layer - SIG1 w20: A46_Rin_1.2@4548.34,711.12 A46_Cin_1.1@4585.23,674.23
RF47: A47_Cin_1.1 A47_Rin_1.2 K1.A5 | length 1080.3
  Top Layer - SIG1 w11: K1.A5@3551.43,1077.95 3769.49,1077.95 A47_Rin_1.2@4342.33,505.11
  Top Layer - SIG1 w20: A47_Rin_1.2@4342.33,505.11 A47_Cin_1.1@4379.22,468.22
RF48: A48_Cin_1.1 A48_Rin_1.2 K1.A4 | length 1022.8
  Top Layer - SIG1 w11: K1.A4@3551.43,977.95 3635.93,977.95 4136.33,477.55 A48_Rin_1.2@4136.33,299.1
  Top Layer - SIG1 w20: A48_Rin_1.2@4136.33,299.1 A48_Cin_1.1@4173.21,262.21
RF49: A49_Cin_1.1 A49_Rin_1.2 K1.R2 | length 893.9
  Bottom Layer - SIG4 w11: A49_Rin_1.2@1772.67,93.06 1772.67,399.19 K1.R2@2151.43,777.95
  Bottom Layer - SIG4 w20: A49_Cin_1.1@1735.79,56.17 A49_Rin_1.2@1772.67,93.06
RF50: A50_Cin_1.1 A50_Rin_1.2 K1.P4 | length 1256.1
  Bottom Layer - SIG4 w11: A50_Rin_1.2@1978.71,-112.98 2201.43,109.74 2201.43,927.95 K1.P4@2251.43,977.95
  Bottom Layer - SIG4 w20: A50_Cin_1.1@1941.83,-149.87 A50_Rin_1.2@1978.71,-112.98
RF51: A51_Cin_1.1 A51_Rin_1.2 K1.N7 | length 1765.2
  Bottom Layer - SIG4 w11: A51_Rin_1.2@2184.72,-313.34 A51_Rin_1.2@2184.72,-318.99 2401.43,-102.28 2401.43,1227.95 K1.N7@2351.43,1277.95
  Bottom Layer - SIG4 w20: A51_Cin_1.1@2147.84,-355.88 A51_Rin_1.2@2184.72,-318.99
RF52: A52_Cin_1.1 A52_Rin_1.2 K1.M7 | length 1921.7
  Bottom Layer - SIG4 w11: A52_Rin_1.2@2390.73,-525 2501.43,-414.29 2501.43,1227.95 K1.M7@2451.43,1277.95
  Bottom Layer - SIG4 w20: A52_Cin_1.1@2353.84,-561.88 A52_Rin_1.2@2390.73,-525
RF53: A53_Cin_1.1 A53_Rin_1.2 K1.E8 | length 2063.1
  Bottom Layer - SIG4 w11: K1.E8@3151.43,1377.95 3101.43,1327.95 3101.43,232.26 3101.43,-314.2 A53_Rin_1.2@3312.23,-525
  Bottom Layer - SIG4 w20: A53_Rin_1.2@3312.23,-525 A53_Cin_1.1@3349.12,-561.88
RF54: A54_Cin_1.1 A54_Rin_1.2 K1.D7 | length 1801
  Bottom Layer - SIG4 w11: K1.D7@3251.43,1277.95 3201.43,1227.95 3201.43,214.98 3201.43,-2.18 A54_Rin_1.2@3518.24,-318.99
  Bottom Layer - SIG4 w20: A54_Rin_1.2@3518.24,-318.99 A54_Cin_1.1@3555.12,-355.88
RF55: A55_Cin_1.1 A55_Rin_1.2 K1.C7 | length 1638.9
  Bottom Layer - SIG4 w11: K1.C7@3351.43,1277.95 3301.43,1227.95 3301.43,309.83 A55_Rin_1.2@3724.24,-112.98
  Bottom Layer - SIG4 w20: A55_Rin_1.2@3724.24,-112.98 A55_Cin_1.1@3761.13,-149.87
RF56: A56_Cin_1.1 A56_Rin_1.2 K1.C5 | length 1276.8
  Bottom Layer - SIG4 w11: K1.C5@3351.43,1077.95 3401.43,1027.95 3401.43,621.91 A56_Rin_1.2@3930.29,93.06
  Bottom Layer - SIG4 w20: A56_Rin_1.2@3930.29,93.06 A56_Cin_1.1@3967.17,56.17
RF57: A57_Cin_1.1 A57_Rin_1.2 K1.B4 | length 1132.7
  Top Layer - SIG1 w11: K1.B4@3451.43,977.95 3498.82,930.57 ; 3500.72,928.67 3500.72,648 3500.72,522.63 3871.19,152.16 A57_Rin_1.2@3930.29,93.06
  Top Layer - SIG1 w20: A57_Rin_1.2@3930.29,93.06 A57_Cin_1.1@3967.17,56.17
RF58: A58_Cin_1.1 A58_Rin_1.2 K1.C6 | length 1497.5
  Top Layer - SIG1 w11: K1.C6@3351.43,1177.95 3401.43,1127.95 3401.43,455.89 3401.43,209.83 3579.8,31.46 A58_Rin_1.2@3724.24,-112.98
  Top Layer - SIG1 w20: A58_Rin_1.2@3724.24,-112.98 A58_Cin_1.1@3761.13,-149.87
RF59: A59_Cin_1.1 A59_Rin_1.2 K1.D6 | length 1659.6
  Top Layer - SIG1 w11: K1.D6@3251.43,1177.95 3301.43,1127.95 3301.43,-102.19 A59_Rin_1.2@3518.24,-318.99
  Top Layer - SIG1 w20: A59_Rin_1.2@3518.24,-318.99 A59_Cin_1.1@3555.12,-355.88
RF60: A60_Cin_1.1 A60_Rin_1.2 K1.D8 | length 2021.7
  Top Layer - SIG1 w11: K1.D8@3251.43,1377.95 3201.43,1327.95 3201.43,482.26 3201.43,-414.2 A60_Rin_1.2@3312.23,-525
  Top Layer - SIG1 w20: A60_Rin_1.2@3312.23,-525 A60_Cin_1.1@3349.12,-561.88
RF61: A61_Cin_1.1 A61_Rin_1.2 K1.L8 | length 2063.1
  Top Layer - SIG1 w11: A61_Rin_1.2@2390.73,-525 2601.43,-314.29 2601.43,382.26 2601.43,1327.95 K1.L8@2551.43,1377.95
  Top Layer - SIG1 w20: A61_Cin_1.1@2353.84,-561.88 A61_Rin_1.2@2390.73,-525
RF62: A62_Cin_1.1 A62_Rin_1.2 K1.M8 | length 1901
  Top Layer - SIG1 w11: A62_Rin_1.2@2184.72,-318.99 2501.43,-2.28 2501.43,364.98 2501.43,1327.95 K1.M8@2451.43,1377.95
  Top Layer - SIG1 w20: A62_Cin_1.1@2147.84,-355.88 A62_Rin_1.2@2184.72,-318.99
RF63: A63_Cin_1.1 A63_Rin_1.2 K1.M6 | length 1538.9
  Top Layer - SIG1 w11: A63_Rin_1.2@1978.71,-112.98 2123.06,31.37 2401.43,309.74 2401.43,556.32 2401.43,1127.95 K1.M6@2451.43,1177.95
  Top Layer - SIG1 w20: A63_Cin_1.1@1941.83,-149.87 A63_Rin_1.2@1978.71,-112.98
RF64: A64_Cin_1.1 A64_Rin_1.2 K1.R3 | length 1035.1
  Top Layer - SIG1 w11: A64_Rin_1.2@1772.67,93.06 1831.68,152.06 2201.07,521.46 2201.07,828.32 K1.R3@2151.43,877.95
  Top Layer - SIG1 w20: A64_Cin_1.1@1735.79,56.17 A64_Rin_1.2@1772.67,93.06
RF-OUT1: A1_L2.2 CONN3.13 | length 810.7
  Top Layer - SIG1 w11: CONN3.13@730.76,-676 1128.11,-278.65 ccw(c1057.4,-207.94) 1157.4,-207.94 A1_L2.2@1157.4,-37.75
RF-OUT2: A2_L2.2 CONN3.15 | length 915.6
  Top Layer - SIG1 w11: CONN3.15@708.49,-653.73 797.12,-565.1 ccw(c726.41,-494.39) 826.41,-494.39 826.41,18.92 cw(c883.47,18.92) 843.12,59.27 A2_L2.2@951.75,167.9
RF-OUT3: A3_L2.2 CONN3.17 | length 1025.7
  Top Layer - SIG1 w11: CONN3.17@686.22,-631.46 716.45,-601.22 ccw(c645.74,-530.51) 745.74,-530.51 A3_L2.2@745.74,373.91
RF-OUT4: A4_L2.2 CONN3.19 | length 1236.3
  Top Layer - SIG1 w11: A4_L2.2@539.74,579.92 539.74,-443.56 ccw(c639.74,-443.56) 569.03,-514.27 CONN3.19@663.95,-609.19
RF-OUT5: A5_L2.2 CONN4.1 | length 1134.4
  Top Layer - SIG1 w11: A5_L2.2@611.99,2248.34 611.99,3271.81 cw(c711.99,3271.81) 641.28,3342.52 CONN4.1@664.21,3365.45
RF-OUT6: A6_L2.2 CONN4.3 | length 983.2
  Top Layer - SIG1 w11: CONN4.3@687.81,3386.39 686.49,3387.71 cw(c649.08,3350.32) 701.97,3350.32 701.97,2611.79 ccw(c801.97,2611.79) 731.26,2541.08 A6_L2.2@818,2454.34
RF-OUT7: A7_L2.2 CONN4.5 | length 871.6
  Top Layer - SIG1 w11: CONN4.5@708.75,3409.99 751.64,3367.11 cw(c680.92,3296.4) 780.92,3296.4 780.92,2944.86 ccw(c880.92,2944.86) 810.21,2874.14 A7_L2.2@1024.01,2660.35
RF-OUT8: A8_L2.2 CONN4.7 | length 768.3
  Top Layer - SIG1 w11: CONN4.7@731.02,3432.26 1200.76,2962.53 cw(c1130.05,2891.82) 1230.05,2891.82 A8_L2.2@1230.05,2866.39
RF-OUT9: A9_L2.2 CONN4.8 | length 987.9
  Top Layer - SIG1 w11: CONN4.8@605.39,3557.18 v3(646.71,3515.86)
  Bottom Layer - SIG4 w11: v3@648.22,3515.05 1129.55,3033.72 cw(c1058.83,2963.01) 1158.83,2963.01 A9_L2.2@1158.83,2792.84
RF-OUT10: A10_L2.2 CONN4.6 | length 1095.8
  Top Layer - SIG1 w11: CONN4.6@583.12,3534.91 v3@646.1,3471.93
  Bottom Layer - SIG4 w11: v3@648.24,3471.72 648.24,2932.78 ccw(c748.24,2932.78) 677.52,2862.07 A10_L2.2@952.79,2586.8
  other v3: 646.71,3472.54
RF-OUT11: A11_L2.2 CONN4.4 | length 1200.3
  Top Layer - SIG1 w11: CONN4.4@560.85,3512.64 cw(c515.14,3466.93) 579.78,3466.93 v3(579.78,3425.29)
  Bottom Layer - SIG4 w11: v3@581.31,3424.48 581.31,2587.7 ccw(c681.31,2587.7) 610.6,2516.99 A11_L2.2@746.79,2380.79
RF-OUT12: A12_L2.2 CONN4.2 | length 1517.1
  Top Layer - SIG1 w11: v3(465.61,3563.34) CONN4.2@538.58,3490.37
  Bottom Layer - SIG4 w11: v3@467.13,3562.52 467.13,2289.85 ccw(c567.13,2289.85) 496.42,2219.14 A12_L2.2@540.78,2174.79
RF-OUT13: A13_L2.2 CONN3.20 | length 1519.8
  Top Layer - SIG1 w11: v3@449.72,-823.41 CONN3.20@538.67,-734.46
  Bottom Layer - SIG4 w11: v3(449.86,-823.55) 449.86,303.85 cw(c549.86,303.85) 479.15,374.57 A13_L2.2@612.12,507.53
RF-OUT14: A14_L2.2 CONN3.18 | length 1156.2
  Top Layer - SIG1 w11: CONN3.18@560.94,-756.74 561.89,-755.79 ccw(c491.18,-685.08) 591.18,-685.08 v3(591.18,-631.46)
  Bottom Layer - SIG4 w11: v3(591.18,-631.46) 591.18,33.16 cw(c691.18,33.16) 620.47,103.87 A14_L2.2@818.12,301.53
RF-OUT15: A15_L2.2 CONN3.16 | length 1183.7
  Top Layer - SIG1 w11: v4(535.45,-826.77) CONN3.16@583.21,-779.01
  Bottom Layer - SIG4 w11: v4(535.45,-826.77) 535.45,-790.16 cw(c635.45,-790.16) 564.74,-719.45 994.84,-289.34 ccw(c924.13,-218.63) 1024.13,-218.63 1024.13,-190.57 A15_L2.2@1024.13,95.52
RF-OUT16: A16_L2.2 CONN3.14 | length 945.4
  Top Layer - SIG1 w11: CONN3.14@605.49,-801.28 605.49,-801.07 v3(646.71,-759.84)
  Bottom Layer - SIG4 w11: v3(646.71,-759.84) 1200.49,-206.06 ccw(c1129.78,-135.35) 1229.78,-135.35 A16_L2.2@1229.78,-110.13
RF-OUT17: A17_L2.2 CONN1.8 | length 987.9
  Top Layer - SIG1 w11: v3(4989.35,3582.48) CONN1.8@5030.67,3623.8
  Bottom Layer - SIG4 w11: A17_L2.2@4267.49,3071.52 4437.66,3071.52 ccw(c4437.66,3171.52) 4508.37,3100.81 v3@4989.7,3582.14
RF-OUT18: A18_L2.2 CONN1.6 | length 1095.8
  Top Layer - SIG1 w11: v3@4945.41,3583.09 CONN1.6@5008.4,3646.07
  Bottom Layer - SIG4 w11: A18_L2.2@4061.45,3277.56 4336.72,3552.83 cw(c4407.43,3482.12) 4407.43,3582.12 v3@4946.37,3582.12
  other v3: 4946.02,3582.48
RF-OUT19: A19_L2.2 CONN1.4 | length 1200.3
  Top Layer - SIG1 w11: v3(4898.78,3649.41) 4940.42,3649.41 ccw(c4940.42,3714.05) CONN1.4@4986.13,3668.34
  Bottom Layer - SIG4 w11: A19_L2.2@3855.45,3483.57 3991.64,3619.76 cw(c4062.35,3549.05) 4062.35,3649.05 v3@4899.13,3649.05
RF-OUT20: A20_L2.2 CONN1.2 | length 1517.1
  Top Layer - SIG1 w11: CONN1.2@4963.85,3690.62 v3(5036.82,3763.58)
  Bottom Layer - SIG4 w11: A20_L2.2@3649.44,3689.58 3693.79,3733.93 cw(c3764.5,3663.22) 3764.5,3763.22 v3@5037.18,3763.22
RF-OUT21: A21_L2.2 CONN4.20 | length 1519.8
  Top Layer - SIG1 w11: v3@650.07,3779.76 CONN4.20@739.02,3690.81
  Bottom Layer - SIG4 w11: v3@651.46,3778.81 1778.86,3778.81 cw(c1778.86,3678.81) 1849.57,3749.52 A21_L2.2@1982.54,3616.55
  other v3: 649.93,3779.62
RF-OUT22: A22_L2.2 CONN4.18 | length 1156.2
  Top Layer - SIG1 w11: CONN4.18@716.75,3668.54 717.69,3667.59 ccw(c788.4,3738.3) 788.4,3638.3 v3@842.02,3638.3
  Bottom Layer - SIG4 w11: v3(843.55,3637.49) 1508.17,3637.49 cw(c1508.17,3537.49) 1578.88,3608.2 A22_L2.2@1776.53,3410.54
RF-OUT23: A23_L2.2 CONN4.16 | length 1183.7
  Top Layer - SIG1 w11: v4(646.71,3694.03) CONN4.16@694.47,3646.27
  Bottom Layer - SIG4 w11: v4@648.24,3693.22 684.85,3693.22 cw(c684.85,3593.22) 755.56,3663.93 1185.66,3233.82 ccw(c1256.37,3304.53) 1256.37,3204.53 1284.44,3204.53 A23_L2.2@1570.53,3204.53
RF-OUT24: A24_L2.2 CONN4.14 | length 945.4
  Top Layer - SIG1 w11: CONN4.14@672.2,3624 672.42,3624 v3(713.64,3582.77)
  Bottom Layer - SIG4 w11: v3@715.16,3581.96 1268.95,3028.17 ccw(c1339.66,3098.88) 1339.66,2998.88 A24_L2.2@1364.88,2998.88
RF-OUT25: A25_L2.2 CONN4.13 | length 810.7
  Top Layer - SIG1 w11: CONN4.13@797.83,3499.08 1195.19,3101.72 ccw(c1265.9,3172.43) 1265.9,3072.43 A25_L2.2@1436.09,3072.43
RF-OUT26: A26_L2.2 CONN4.15 | length 915.6
  Top Layer - SIG1 w11: CONN4.15@820.11,3521.35 908.73,3432.72 ccw(c979.44,3503.43) 979.44,3403.43 1492.75,3403.43 cw(c1492.75,3346.36) 1533.11,3386.72 A26_L2.2@1641.74,3278.09
RF-OUT27: A27_L2.2 CONN4.17 | length 1025.7
  Top Layer - SIG1 w11: CONN4.17@842.38,3543.62 872.61,3513.38 ccw(c943.32,3584.09) 943.32,3484.09 A27_L2.2@1847.75,3484.09
RF-OUT28: A28_L2.2 CONN4.19 | length 1236.3
  Top Layer - SIG1 w11: CONN4.19@864.65,3565.89 959.57,3660.81 cw(c1030.28,3590.1) 1030.28,3690.1 A28_L2.2@2053.75,3690.1
RF-OUT29: A29_L2.2 CONN1.1 | length 1134.4
  Top Layer - SIG1 w11: A29_L2.2@3721.82,3617.2 4745.29,3617.2 cw(c4745.29,3517.2) 4816,3587.91 CONN1.1@4838.93,3564.98
RF-OUT30: A30_L2.2 CONN1.3 | length 983.2
  Top Layer - SIG1 w11: A30_L2.2@3927.83,3411.19 4014.56,3497.93 cw(c4085.27,3427.22) 4085.27,3527.22 4823.8,3527.22 ccw(c4823.8,3580.11) 4861.19,3542.69 CONN1.3@4859.87,3541.38
RF-OUT31: A31_L2.2 CONN1.5 | length 871.6
  Top Layer - SIG1 w11: A31_L2.2@4133.83,3205.18 4347.63,3418.97 cw(c4418.34,3348.26) 4418.34,3448.26 4769.88,3448.26 ccw(c4769.88,3548.26) 4840.59,3477.55 CONN1.5@4883.47,3520.44
RF-OUT32: A32_L2.2 CONN1.7 | length 768.3
  Top Layer - SIG1 w11: A32_L2.2@4339.87,2999.14 4365.3,2999.14 ccw(c4365.3,3099.14) 4436.01,3028.43 CONN1.7@4905.74,3498.17
RF-OUT33: A33_L2.2 CONN2.8 | length 987.9
  Top Layer - SIG1 w11: v3(5056.16,-759.96) CONN2.8@5097.48,-801.28
  Bottom Layer - SIG4 w11: A33_L2.2@4545.17,-38.14 4545.17,-208.31 ccw(c4645.17,-208.31) 4574.46,-279.02 v3@5055.79,-760.35
RF-OUT34: A34_L2.2 CONN2.6 | length 1095.8
  Top Layer - SIG1 w11: v3@5056.77,-716.03 CONN2.6@5119.75,-779.01
  Bottom Layer - SIG4 w11: A34_L2.2@4751.21,167.9 5026.48,-107.37 cw(c4955.77,-178.08) 5055.77,-178.08 v3@5055.77,-717.02
  other v3: 5056.16,-716.63
RF-OUT35: A35_L2.2 CONN2.4 | length 1200.3
  Top Layer - SIG1 w11: v3(5123.09,-669.39) 5123.09,-711.03 ccw(c5187.73,-711.03) CONN2.4@5142.02,-756.74
  Bottom Layer - SIG4 w11: A35_L2.2@4957.22,373.91 5093.41,237.72 cw(c5022.7,167.01) 5122.7,167.01 v3@5122.7,-669.77
RF-OUT36: A36_L2.2 CONN2.2 | length 1517.1
  Top Layer - SIG1 w11: CONN2.2@5164.29,-734.47 v3(5237.26,-807.44)
  Bottom Layer - SIG4 w11: A36_L2.2@5163.22,579.92 5207.58,535.56 cw(c5136.87,464.85) 5236.87,464.85 v3@5236.87,-807.82
RF-OUT37: A37_L2.2 CONN1.20 | length 1519.8
  Top Layer - SIG1 w11: CONN1.20@5164.29,3490.18 v3@5253.24,3579.12
  Bottom Layer - SIG4 w11: A37_L2.2@5091.2,2247.82 5224.17,2380.78 ccw(c5153.46,2451.5) 5253.46,2451.5 v3@5253.46,3578.9
  other v3: 5253.11,3579.26
RF-OUT38: A38_L2.2 CONN1.18 | length 1156.2
  Top Layer - SIG1 w11: v3@5111.79,3387.17 5111.79,3440.79 cw(c5211.79,3440.79) 5141.08,3511.5 CONN1.18@5142.02,3512.45
  Bottom Layer - SIG4 w11: A38_L2.2@4885.19,2453.82 5082.85,2651.48 ccw(c5012.14,2722.19) 5112.14,2722.19 v3(5112.14,3386.81)
RF-OUT39: A39_L2.2 CONN1.16 | length 1183.7
  Top Layer - SIG1 w11: CONN1.16@5119.75,3534.72 v4(5167.52,3582.48)
  Bottom Layer - SIG4 w11: A39_L2.2@4679.19,2659.83 4679.19,2945.92 4679.19,2973.98 cw(c4779.19,2973.98) 4708.47,3044.69 5138.58,3474.8 ccw(c5067.87,3545.51) 5167.87,3545.51 v4@5167.87,3582.12
RF-OUT40: A40_L2.2 CONN1.14 | length 945.4
  Top Layer - SIG1 w11: v3(5056.26,3515.55) 5097.48,3556.78 CONN1.14@5097.48,3556.99
  Bottom Layer - SIG4 w11: A40_L2.2@4473.53,2865.48 4473.53,2890.7 cw(c4573.53,2890.7) 4502.82,2961.41 v3@5056.61,3515.19
RF-OUT41: A41_L2.2 CONN1.13 | length 810.7
  Top Layer - SIG1 w11: A41_L2.2@4545.91,2793.1 4545.91,2963.29 cw(c4645.91,2963.29) 4575.2,3034 CONN1.13@4972.56,3431.35
RF-OUT42: A42_L2.2 CONN1.15 | length 915.6
  Top Layer - SIG1 w11: A42_L2.2@4751.57,2587.45 4860.2,2696.08 ccw(c4819.84,2736.43) 4876.91,2736.43 4876.91,3249.74 cw(c4976.91,3249.74) 4906.2,3320.45 CONN1.15@4994.83,3409.08
RF-OUT43: A43_L2.2 CONN1.17 | length 1025.7
  Top Layer - SIG1 w11: A43_L2.2@4957.57,2381.44 4957.57,3285.86 cw(c5057.57,3285.86) 4986.86,3356.57 CONN1.17@5017.1,3386.81
RF-OUT44: A44_L2.2 CONN2.1 | length 1134.4
  Top Layer - SIG1 w11: CONN2.1@5038.63,-609.58 5061.55,-586.65 ccw(c4990.84,-515.94) 5090.84,-515.94 A44_L2.2@5090.84,507.54
RF-OUT45: A45_L2.2 CONN1.19 | length 1236.3
  Top Layer - SIG1 w11: CONN1.19@5039.37,3364.54 5134.29,3269.62 cw(c5063.58,3198.91) 5163.58,3198.91 A45_L2.2@5163.58,2175.43
RF-OUT46: A46_L2.2 CONN2.3 | length 983.2
  Top Layer - SIG1 w11: A46_L2.2@4884.84,301.53 4971.57,214.79 cw(c4900.86,144.08) 5000.86,144.08 5000.86,-594.44 ccw(c5053.76,-594.44) 5016.34,-631.83 CONN2.3@5015.02,-630.51
RF-OUT47: A47_L2.2 CONN2.5 | length 871.6
  Top Layer - SIG1 w11: A47_L2.2@4678.83,95.52 4892.62,-118.27 cw(c4821.91,-188.98) 4921.91,-188.98 4921.91,-540.52 ccw(c5021.91,-540.52) 4951.2,-611.23 CONN2.5@4994.08,-654.12
RF-OUT48: A48_L2.2 CONN2.7 | length 768.3
  Top Layer - SIG1 w11: A48_L2.2@4472.79,-110.52 4472.79,-135.94 ccw(c4572.79,-135.94) 4502.08,-206.65 CONN2.7@4971.81,-676.39
RF-OUT49: A49_L2.2 CONN3.8 | length 987.9
  Top Layer - SIG1 w11: CONN3.8@672.3,-868.09 v3(713.62,-826.77)
  Bottom Layer - SIG4 w11: v3(713.62,-826.77) 1194.95,-345.46 cw(c1265.66,-416.17) 1265.66,-316.17 A49_L2.2@1435.82,-316.17
RF-OUT50: A50_L2.2 CONN3.6 | length 1095.8
  Top Layer - SIG1 w11: CONN3.6@694.57,-890.36 v3@757.55,-827.38
  Bottom Layer - SIG4 w11: v3(756.95,-826.77) 1295.88,-826.77 ccw(c1295.88,-726.77) 1366.6,-797.48 A50_L2.2@1641.86,-522.21
RF-OUT51: A51_L2.2 CONN3.4 | length 1200.3
  Top Layer - SIG1 w11: CONN3.4@716.84,-912.63 cw(c762.55,-958.34) 762.55,-893.7 v3(804.19,-893.7)
  Bottom Layer - SIG4 w11: v3(804.19,-893.7) 1640.97,-893.7 ccw(c1640.97,-793.7) 1711.68,-864.41 A51_L2.2@1847.87,-728.22
RF-OUT52: A52_L2.2 CONN3.2 | length 1517.1
  Top Layer - SIG1 w11: v3(666.14,-1007.87) CONN3.2@739.11,-934.9
  Bottom Layer - SIG4 w11: v3(666.14,-1007.87) 1938.81,-1007.87 ccw(c1938.81,-907.87) 2009.52,-978.58 A52_L2.2@2053.88,-934.23
RF-OUT53: A53_L2.2 CONN2.20 | length 1519.8
  Top Layer - SIG1 w11: CONN2.20@4963.85,-934.91 v3@5052.8,-1023.86
  Bottom Layer - SIG4 w11: A53_L2.2@3721.46,-861.85 3854.43,-994.82 ccw(c3925.14,-924.11) 3925.14,-1024.11 v3@5052.54,-1024.11
  other v3: 5052.94,-1023.72
RF-OUT54: A54_L2.2 CONN2.18 | length 1156.2
  Top Layer - SIG1 w11: v3(4860.85,-882.4) 4914.47,-882.4 cw(c4914.47,-982.4) 4985.18,-911.69 CONN2.18@4986.13,-912.64
  Bottom Layer - SIG4 w11: A54_L2.2@3927.47,-655.84 4125.12,-853.49 ccw(c4195.83,-782.78) 4195.83,-882.78 v3@4860.46,-882.78
RF-OUT55: A55_L2.2 CONN2.16 | length 1183.7
  Top Layer - SIG1 w11: CONN2.16@5008.4,-890.36 v4(5056.16,-938.13)
  Bottom Layer - SIG4 w11: A55_L2.2@4133.48,-449.83 4419.57,-449.83 4447.63,-449.83 cw(c4447.63,-549.83) 4518.34,-479.12 4948.44,-909.22 ccw(c5019.15,-838.51) 5019.15,-938.51 v4@5055.77,-938.51
RF-OUT56: A56_L2.2 CONN2.14 | length 945.4
  Top Layer - SIG1 w11: v3(4989.23,-826.87) 5030.46,-868.09 CONN2.14@5030.67,-868.09
  Bottom Layer - SIG4 w11: A56_L2.2@4339.13,-244.18 4364.34,-244.18 cw(c4364.34,-344.18) 4435.05,-273.47 v3@4988.84,-827.25
RF-OUT57: A57_L2.2 CONN2.13 | length 810.7
  Top Layer - SIG1 w11: A57_L2.2@4266.75,-316.56 4436.93,-316.56 cw(c4436.93,-416.56) 4507.65,-345.85 CONN2.13@4905,-743.2
RF-OUT58: A58_L2.2 CONN2.15 | length 915.6
  Top Layer - SIG1 w11: A58_L2.2@4061.09,-522.21 4169.73,-630.84 ccw(c4210.08,-590.49) 4210.08,-647.56 4723.39,-647.56 cw(c4723.39,-747.56) 4794.1,-676.85 CONN2.15@4882.73,-765.47
RF-OUT59: A59_L2.2 CONN2.17 | length 1025.7
  Top Layer - SIG1 w11: A59_L2.2@3855.09,-728.22 4759.51,-728.22 cw(c4759.51,-828.22) 4830.22,-757.51 CONN2.17@4860.46,-787.75
RF-OUT60: A60_L2.2 CONN2.19 | length 1236.3
  Top Layer - SIG1 w11: A60_L2.2@3649.08,-934.23 4672.55,-934.23 ccw(c4672.55,-834.23) 4743.26,-904.94 CONN2.19@4838.19,-810.02
RF-OUT61: A61_L2.2 CONN3.1 | length 1134.4
  Top Layer - SIG1 w11: CONN3.1@864.39,-809.63 887.32,-832.56 ccw(c958.03,-761.85) 958.03,-861.85 A61_L2.2@1981.5,-861.85
RF-OUT62: A62_L2.2 CONN3.3 | length 983.2
  Top Layer - SIG1 w11: CONN3.3@843.45,-786.03 CONN3.3@842.12,-787.36 cw(c879.52,-824.76) 879.52,-771.87 1618.04,-771.87 ccw(c1618.04,-671.87) 1688.76,-742.58 A62_L2.2@1775.49,-655.84
RF-OUT63: A63_L2.2 CONN3.5 | length 871.6
  Top Layer - SIG1 w11: CONN3.5@819.84,-765.09 862.73,-722.2 cw(c933.44,-792.91) 933.44,-692.91 1284.98,-692.91 ccw(c1284.98,-592.91) 1355.69,-663.62 A63_L2.2@1569.48,-449.83
RF-OUT64: A64_L2.2 CONN3.7 | length 768.3
  Top Layer - SIG1 w11: CONN3.7@797.57,-742.82 1267.31,-273.08 cw(c1338.02,-343.79) 1338.02,-243.79 A64_L2.2@1363.44,-243.79
pads on no net: CONN1.0@4892.86,3719.85 CONN1.0@5193.52,3419.19 CONN2.0@4892.87,-964.14 CONN2.0@5193.52,-663.48 CONN3.0@509.44,-663.48 CONN3.0@810.1,-964.14 CONN4.0@509.35,3419.38 CONN4.0@810.01,3720.04 FID1.0 FID2.0 FID3.0 K1.E5 K1.E6 K1.E7 K1.E9 K1.E10 K1.E11 K1.F5 K1.F6 K1.F7 K1.F8 K1.F9 K1.F10 K1.F11 K1.G5 K1.G6 K1.G7 K1.G8 K1.G9 K1.G10 K1.G11 K1.H6 K1.H7 K1.H8 K1.H9 K1.H10 K1.J5 K1.J6 K1.J7 K1.J8 K1.J9 K1.J10 K1.J11 K1.K5 K1.K6 K1.K7 K1.K8 K1.K9 K1.K10 K1.K11 K1.L5 K1.L6 K1.L7 K1.L9 K1.L10 K1.L11

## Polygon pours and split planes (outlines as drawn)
GND on Top Layer - SIG1 "Bottom Layer - SIG4-No Net" (solid, remove dead copper, pour order 28): 371.12,2067.05 371.12,688.98 193.95,688.98 193.95,2067.05
GND on Top Layer - SIG1 "Bottom Layer - SIG4-No Net" (solid, remove dead copper, pour order 26): 3540.53,3858.27 2162.46,3858.27 2162.46,4035.43 3540.53,4035.43
GND on Top Layer - SIG1 "Bottom Layer - SIG4-No Net" (solid, remove dead copper, pour order 24): 5331.75,688.86 5331.75,2066.93 5508.91,2066.93 5508.91,688.86
3V3 on Top Layer - SIG1 "Bottom Layer - SIG4-No Net" (solid, remove dead copper, pour order 18): 395.72,2066.93 395.72,688.98 436.57,688.98 786.44,1038.85 784.5,1377.95 784.5,1719 436.57,2066.93
3V3 on Top Layer - SIG1 "Bottom Layer - SIG4-No Net" (solid, remove dead copper, pour order 14): 3540.41,3833.66 2162.46,3833.66 2162.46,3792.82 2512.33,3442.95 2851.43,3444.88 3192.48,3444.88 3540.41,3792.82
3V3 on Top Layer - SIG1 "Bottom Layer - SIG4-No Net" (solid, remove dead copper, pour order 10): 5307.14,688.98 5307.14,2066.93 5266.3,2066.93 4916.43,1717.06 4918.36,1377.95 4918.36,1036.91 5266.3,688.98
3V3 on Top Layer - SIG1 "Bottom Layer - SIG4-No Net" (solid, remove dead copper, pour order 8): 2162.46,-1077.76 3540.41,-1077.76 3540.41,-1036.91 3190.54,-687.04 2851.43,-688.98 2510.39,-688.98 2162.46,-1036.91
GND on Top Layer - SIG1 "Bottom Layer - SIG4-No Net" (solid, remove dead copper, pour order 0): 2162.34,-1102.36 3540.41,-1102.36 3540.41,-1279.53 2162.34,-1279.53
GND on Top Layer - SIG1 "L1-GND" (solid, remove dead copper, pour order 36): -475.24,0 -475.24,2755.91 1473.48,4704.63 4229.39,4704.63 6178.11,2755.91 6178.11,0 4229.39,-1948.72 1473.48,-1948.72 -475.24,0
3V3 on Top Layer - SIG1 "Bottom Layer - SIG4-No Net" (solid, remove dead copper, pour order 52): 5307.14,688.98 5307.14,2066.93 5266.3,2066.93 4916.43,1717.06 4918.36,1377.95 4918.36,1036.91 5266.3,688.98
